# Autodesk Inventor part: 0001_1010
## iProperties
Created: 2006-07
Part Number: 0001_1010
Cost Center: 6,812 kg
Material: 1.0570 St 52-3
Document SubType Name: Modeling
Designer: Konrad
Authority: 868887 mm^3
Manufacturer: Standard
Standards Organization: Custom
VerschleissPrioritaet: 0
Gewicht: 0
Flaeche: 000,0E+0 mm^2
Masse: 0,000 kg
Volumen: 000,0E+0 mm^3
Laenge: 300,000 mm
D_Auss: 40,000 mm
D_Inn: 20,000 mm
SaveDate: 2006-07-23
SaveTime: 14:37
TotalMass: 6,812 kg
TotalVolume: 868887 mm^3
Author: Konrad
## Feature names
1. Drehung1 [Revolution]
2. Trennen1
3. Rundung2 [Fillet]
4. Wandstärke2
